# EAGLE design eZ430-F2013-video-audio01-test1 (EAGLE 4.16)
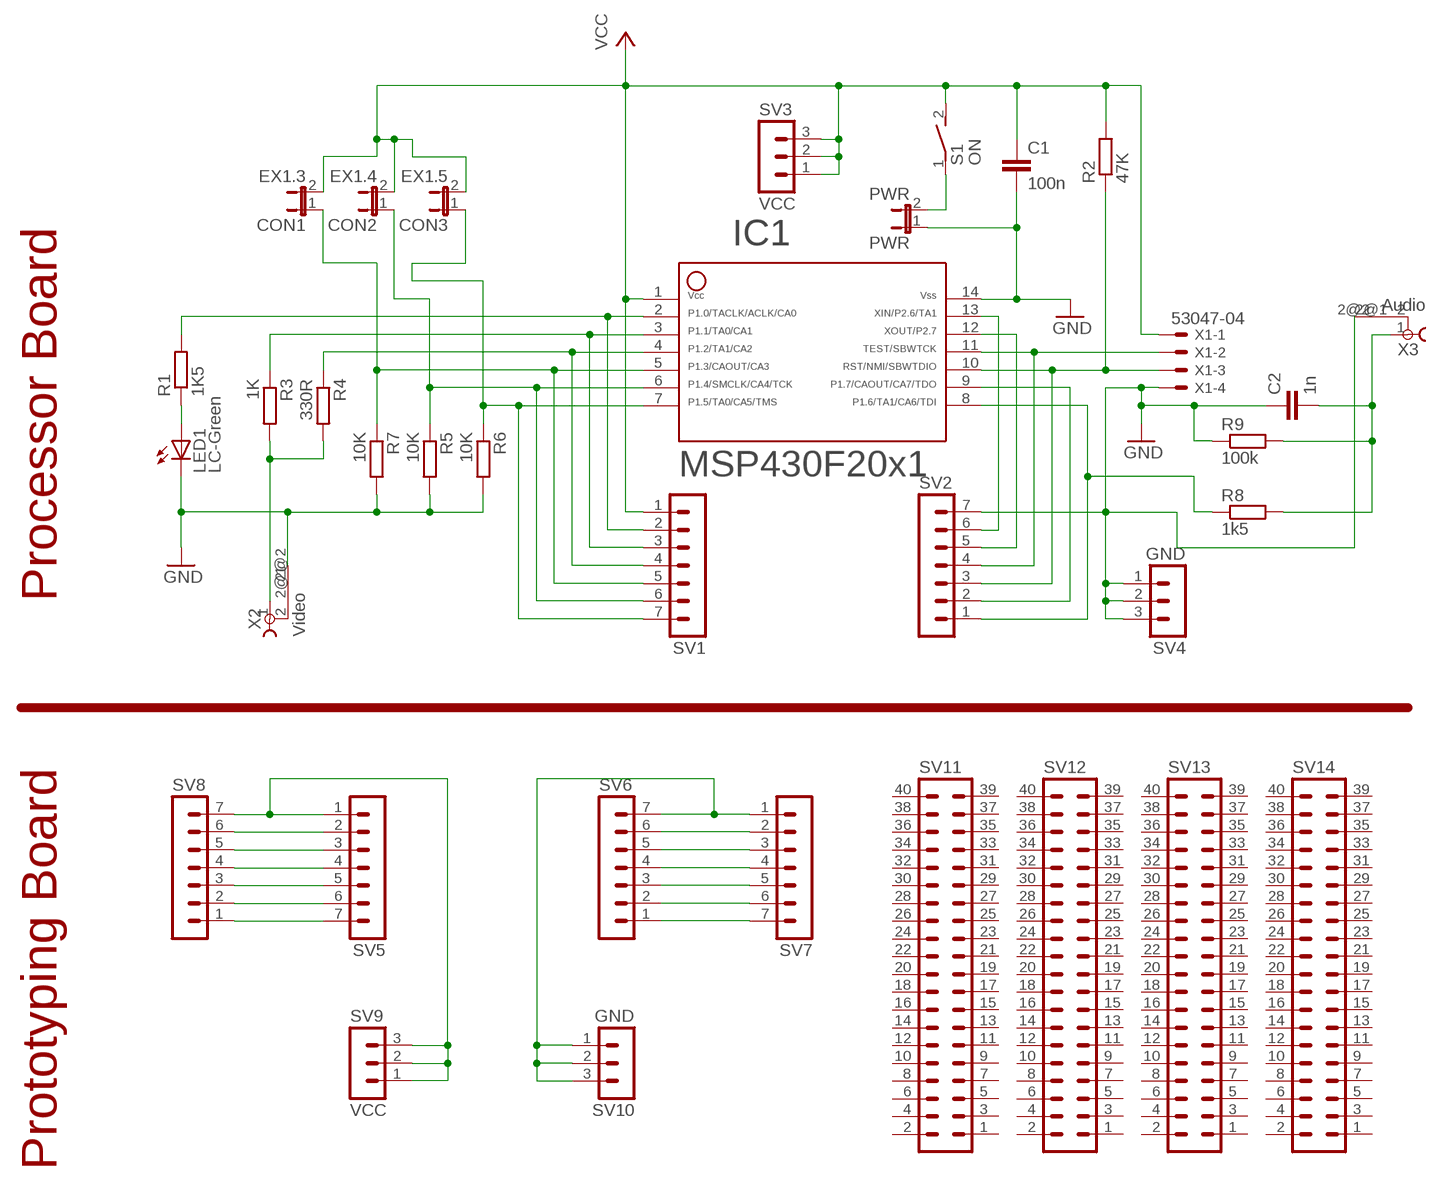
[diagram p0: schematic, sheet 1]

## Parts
C1  100n  C-EU050-030X075  [C050-030X075]
C2  1n  C-EU050-030X075  [C050-030X075]
CON1  EX1.3  JP1E  [JP1]
CON2  EX1.4  JP1E  [JP1]
CON3  EX1.5  JP1E  [JP1]
IC1  F20X1---N14  [N14]
LED1  LC-Green  LED5MM  [LED5MM]
PWR  PWR  JP1E  [JP1]
R1  1K5  R-EU_0204/7  [0204/7]
R2  47K  R-EU_0204/7  [0204/7]
R3  1K  R-EU_0204/7  [0204/7]
R4  330R  R-EU_0204/7  [0204/7]
R5  10K  R-EU_0204/7  [0204/7]
R6  10K  R-EU_0204/7  [0204/7]
R7  10K  R-EU_0204/7  [0204/7]
R8  1k5  R-EU_0204/7  [0204/7]
R9  100k  R-EU_0204/7  [0204/7]
S1  ON  DS01E  [DS-01]
SV1  MA07-1  [MA07-1]
SV2  MA07-1  [MA07-1]
SV3  VCC  MA03-1  [MA03-1]
SV4  GND  MA03-1  [MA03-1]
SV5  MA07-1  [MA07-1]
SV6  MA07-1  [MA07-1]
SV7  MA07-1  [MA07-1]
SV8  MA07-1  [MA07-1]
SV9  VCC  MA03-1  [MA03-1]
SV10  GND  MA03-1  [MA03-1]
SV11  MA20-2  [MA20-2]
SV12  MA20-2  [MA20-2]
SV13  MA20-2  [MA20-2]
SV14  MA20-2  [MA20-2]
X1  53047-04  [53047-04]
X2  Video  TOBU3  [TOBU3]
X3  Audio  TOBU3  [TOBU3]

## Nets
3V_IN: PWR.2 S1.1
AUDIO: C2.2 R8.2 R9.2 X3.1
GND: C1.2 C2.1 IC1.14 LED1.K(C) PWR.1 R5.2 R6.2 R7.2 R9.1 SV2.7 SV4.1 SV4.2 SV4.3 X1.4 X2.2@2 X3.2@2
GND_EX: SV6.7 SV7.1 SV10.1 SV10.2 SV10.3
LED-IN: LED1.A R1.1
N$2: SV6.6 SV7.2
N$3: SV6.5 SV7.3
N$4: SV6.4 SV7.4
N$5: SV6.3 SV7.5
N$6: SV6.2 SV7.6
N$7: SV6.1 SV7.7
N$8: SV5.7 SV8.1
N$9: SV5.6 SV8.2
N$10: SV5.5 SV8.3
N$11: SV5.4 SV8.4
N$12: SV5.3 SV8.5
N$13: SV5.2 SV8.6
P1.0: IC1.2 R1.2 SV1.2
P1.1: IC1.3 R3.1 SV1.3
P1.2: IC1.4 R4.1 SV1.4
P1.3: CON1.1 IC1.5 R7.1 SV1.5
P1.4: CON2.1 IC1.6 R5.1 SV1.6
P1.5: CON3.1 IC1.7 R6.1 SV1.7
P1.6: IC1.8 R8.1 SV2.1
P1.7: IC1.9 SV2.2
SBWTCK: IC1.11 SV2.4 X1.2
SBWTDIO: IC1.10 R2.1 SV2.3 X1.3
VCC: C1.1 CON1.2 CON2.2 CON3.2 IC1.1 R2.2 S1.2 SV1.1 SV3.1 SV3.2 SV3.3 X1.1
VCC-EX: SV5.1 SV8.7 SV9.1 SV9.2 SV9.3
VIDEOOUT: R3.2 R4.2 X2.1
XIN: IC1.13 SV2.6
XOUT: IC1.12 SV2.5
Unconnected: SV11.1 SV11.2 SV11.3 SV11.4 SV11.5 SV11.6 SV11.7 SV11.8 SV11.9 SV11.10 SV11.11 SV11.12 SV11.13 SV11.14 SV11.15 SV11.16 SV11.17 SV11.18 SV11.19 SV11.20 SV11.21 SV11.22 SV11.23 SV11.24 SV11.25 SV11.26 SV11.27 SV11.28 SV11.29 SV11.30 SV11.31 SV11.32 SV11.33 SV11.34 SV11.35 SV11.36 SV11.37 SV11.38 SV11.39 SV11.40 SV12.1 SV12.2 SV12.3 SV12.4 SV12.5 SV12.6 SV12.7 SV12.8 SV12.9 SV12.10 SV12.11 SV12.12 SV12.13 SV12.14 SV12.15 SV12.16 SV12.17 SV12.18 SV12.19 SV12.20 SV12.21 SV12.22 SV12.23 SV12.24 SV12.25 SV12.26 SV12.27 SV12.28 SV12.29 SV12.30 SV12.31 SV12.32 SV12.33 SV12.34 SV12.35 SV12.36 SV12.37 SV12.38 SV12.39 SV12.40 SV13.1 SV13.2 SV13.3 SV13.4 SV13.5 SV13.6 SV13.7 SV13.8 SV13.9 SV13.10 SV13.11 SV13.12 SV13.13 SV13.14 SV13.15 SV13.16 SV13.17 SV13.18 SV13.19 SV13.20 SV13.21 SV13.22 SV13.23 SV13.24 SV13.25 SV13.26 SV13.27 SV13.28 SV13.29 SV13.30 SV13.31 SV13.32 SV13.33 SV13.34 SV13.35 SV13.36 SV13.37 SV13.38 SV13.39 SV13.40 SV14.1 SV14.2 SV14.3 SV14.4 SV14.5 SV14.6 SV14.7 SV14.8 SV14.9 SV14.10 SV14.11 SV14.12 SV14.13 SV14.14 SV14.15 SV14.16 SV14.17 SV14.18 SV14.19 SV14.20 SV14.21 SV14.22 SV14.23 SV14.24 SV14.25 SV14.26 SV14.27 SV14.28 SV14.29 SV14.30 SV14.31 SV14.32 SV14.33 SV14.34 SV14.35 SV14.36 SV14.37 SV14.38 SV14.39 SV14.40 X2.2 X2.2@1 X3.2 X3.2@1

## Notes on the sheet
- Processor Board
- Prototyping Board

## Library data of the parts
C1 C2 = rcl:C-EU: CAPACITOR, European symbol
CON1-CON3 PWR = jumper:JP1E: JUMPER
IC1 = TI_MSP430_v122:F20X1---N14: ***MSP430F20x1***N14
LED1 = led:LED: LED
R1-R9 = rcl:R-EU_: RESISTOR, European symbol
S1 = switch-dil:DS01E: DIL/CODE SWITCH
SV1 SV2 SV5-SV8 = con-lstb:MA07-1: PIN HEADER
SV3 SV4 SV9 SV10 = con-lstb:MA03-1: PIN HEADER
SV11-SV14 = con-lstb:MA20-2: PIN HEADER
X1 = con-molex:53?-04: CONNECTOR wire to board 1.25 mm (.049 inch) pitch header
X2 X3 = con-hirschmann:TOBU3: Female Cinch CONNECTOR

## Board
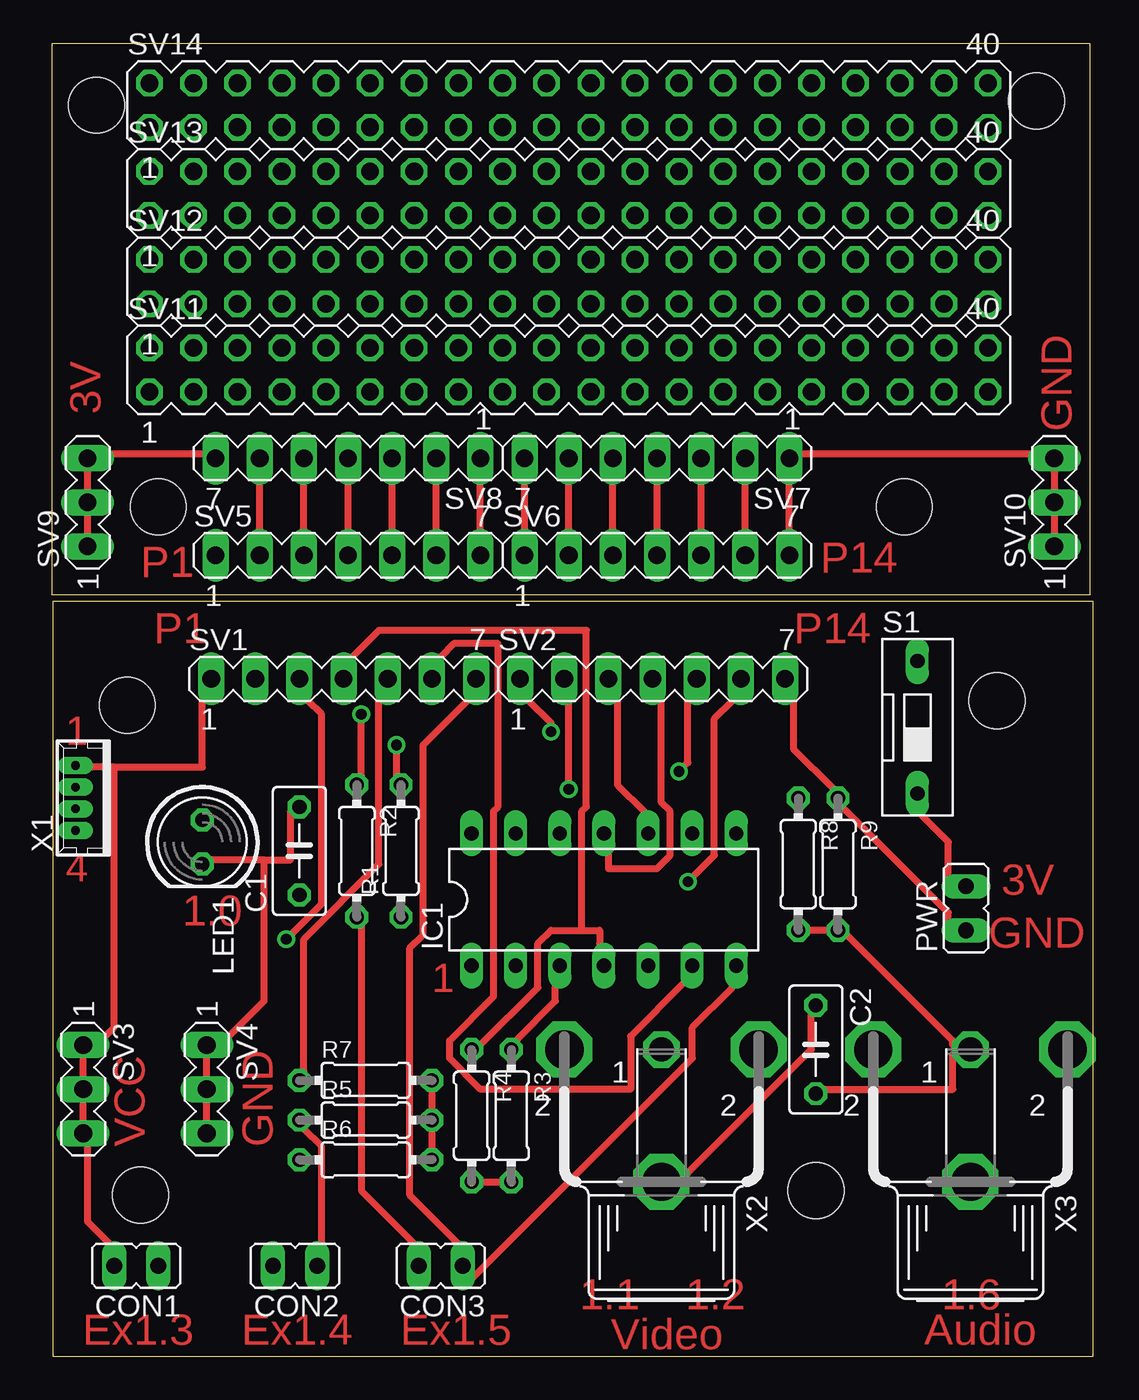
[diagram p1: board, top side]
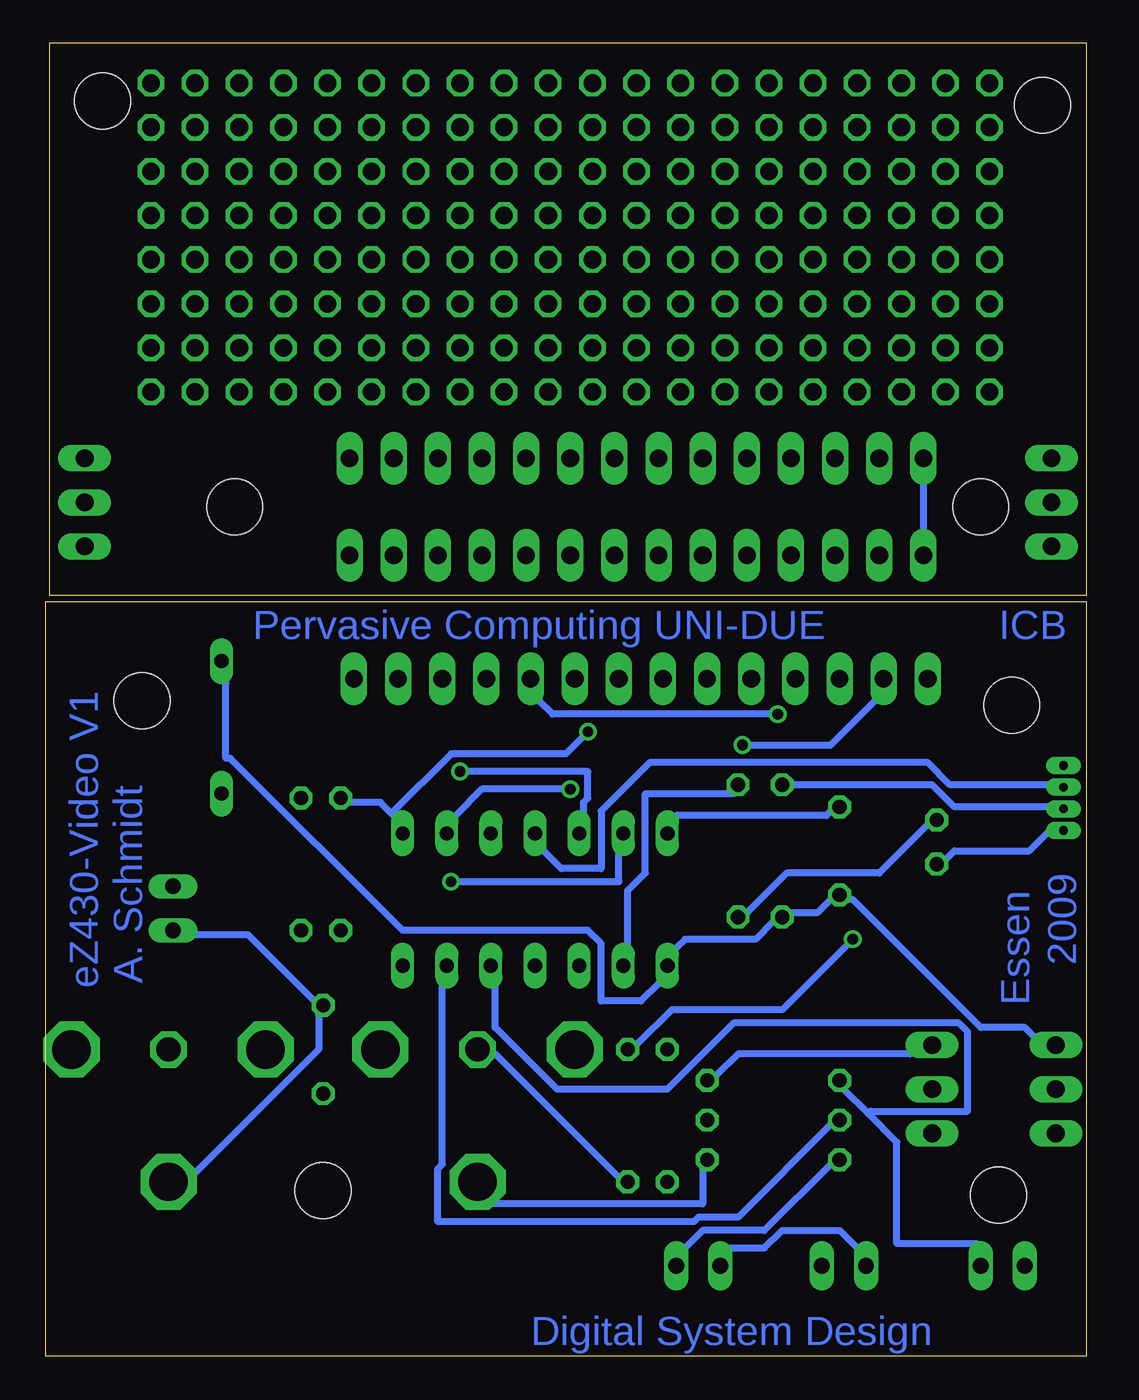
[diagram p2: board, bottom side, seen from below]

Size 59.91 x 75.56 mm. Coordinates in mm from the lower left corner, seen from the top.
Outline: 0.04,0 59.91,0 59.91,43.42 0.04,43.42 0.04,0
Outline: 0,75.56 59.69,75.56 59.69,43.81 0,43.81 0,75.56
Copper layers (1*16): Top 0.035mm / dielectric 1.5mm / Bottom 0.035mm
Design rules "default": minimum track width 16mil, minimum drill 24mil, track to track 12mil, track to pad 12mil, pad to pad 8mil, via to via 8mil, smd to smd 8mil, copper to edge 40mil, drill to drill 8mil, minimum pad ring 10mil, minimum via ring 8mil, stop-mask expansion 4mil, vias tented up to drill 0mil, thermal gap 10mil
Holes 3.2 mm at 4.32,37.46 5.08,9.27 43.94,9.52 54.36,37.71 2.54,72 6.1,48.89 49.02,48.89 56.64,72.26

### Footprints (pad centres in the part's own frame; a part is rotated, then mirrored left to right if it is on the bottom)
C050-030X075 = drill 0.813 octagon: 1 -2.54,0; 2 2.54,0
JP1 = drill 0.914 long: 1 0,-1.27; 2 0,1.27
N14 = drill 0.813 long: 1 -7.625,-3.81; 2 -5.085,-3.81; 3 -2.545,-3.81; 4 -0.005,-3.81; 5 2.535,-3.81; 6 5.075,-3.81; 7 7.615,-3.81; 8 7.615,3.81; 9 5.075,3.81; 10 2.535,3.81; 11 -0.005,3.81; 12 -2.545,3.81; 13 -5.085,3.81; 14 -7.625,3.81
LED5MM = drill 0.813 octagon: A -1.27,0; K 1.27,0
0204/7 = drill 0.813 octagon: 1 -3.81,0; 2 3.81,0
DS-01 = drill 0.813 long: 1 0,-3.81; 2 0,3.81
MA07-1 = drill 1.016 long: 1 -7.62,0; 2 -5.08,0; 3 -2.54,0; 4 0,0; 5 2.54,0; 6 5.08,0; 7 7.62,0
MA03-1 = drill 1.016 long: 1 -2.54,0; 2 0,0; 3 2.54,0
MA20-2 = drill 1.016 octagon: 1 -24.13,-1.27; 2 -24.13,1.27; 3 -21.59,-1.27; 4 -21.59,1.27; 5 -19.05,-1.27; 6 -19.05,1.27; 7 -16.51,-1.27; 8 -16.51,1.27; 9 -13.97,-1.27; 10 -13.97,1.27; 11 -11.43,-1.27; 12 -11.43,1.27; 13 -8.89,-1.27; 14 -8.89,1.27; 15 -6.35,-1.27; 16 -6.35,1.27; 17 -3.81,-1.27; 18 -3.81,1.27; 19 -1.27,-1.27; 20 -1.27,1.27; 21 1.27,-1.27; 22 1.27,1.27; 23 3.81,-1.27; 24 3.81,1.27; 25 6.35,-1.27; 26 6.35,1.27; 27 8.89,-1.27; 28 8.89,1.27; 29 11.43,-1.27; 30 11.43,1.27; 31 13.97,-1.27; 32 13.97,1.27; 33 16.51,-1.27; 34 16.51,1.27; 35 19.05,-1.27; 36 19.05,1.27; 37 21.59,-1.27; 38 21.59,1.27; 39 24.13,-1.27; 40 24.13,1.27
53047-04 = drill 0.5 pad 0.698 long: 1 1.875,0.45; 2 0.625,0.45; 3 -0.625,0.45; 4 -1.875,0.45
TOBU3 = drill 1.397 octagon: 1 0,-2.54 | drill 2.21 octagon: 2 5.588,-2.54; 2@1 -5.588,-2.54; 2@2 0,5.08

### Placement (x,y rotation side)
C1  14.22,29.08 90 top
C2  43.94,17.65 270 top
CON1  4.83,5.2 90 top
CON2  13.97,5.2 90 top
CON3  22.35,5.2 90 top
IC1  31.75,26.28 0 top
LED1  8.64,29.59 270 top
PWR  52.58,25.78 0 top
R1  20.07,29.08 90 top
R2  17.53,29.08 270 top
R3  26.42,13.84 270 top
R4  24.13,13.84 270 top
R5  18.03,13.58 0 top
R6  18.03,11.3 0 top
R7  18.03,15.87 0 top
R8  42.93,28.32 270 top
R9  45.21,28.32 270 top
S1  49.78,36.19 0 top
SV1  16.76,38.98 0 top
SV2  34.54,38.98 0 top
SV3  1.78,15.36 270 top
SV4  8.89,15.36 270 top
SV5  17.02,46.1 0 top
SV6  34.8,46.1 0 top
SV7  34.8,51.68 180 top
SV8  17.02,51.68 180 top
SV9  2.03,49.14 90 top
SV10  57.66,49.14 90 top
SV11  29.72,56.76 0 top
SV12  29.72,61.84 0 top
SV13  29.72,66.92 0 top
SV14  29.72,72 0 top
X1  1.78,32.13 90 top
X2  35.05,15.11 180 top
X3  52.83,15.11 180 top

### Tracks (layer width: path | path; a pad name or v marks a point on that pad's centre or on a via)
3V_IN
  Top 0.406: S1.1 50.04,31.11 51.56,29.59 51.56,27.55 PWR.2
AUDIO
  Top 0.406: R8.2 R9.2 45.72,24.25 51.82,18.16 51.82,17.9 X3.1 51.82,17.39 51.82,15.36 44.45,15.36 C2.2
GND
  Top 0.406: R6.2 R5.2 R7.2 | SV4.3 SV4.2 SV4.1 10.16,18.41 12.19,20.44 12.19,28.57 | 12.19,28.57 13.72,28.57 13.72,31.36 C1.2 | 12.19,28.57 9.14,28.57 LED1.K | SV2.7 42.67,37.71 42.67,34.92 44.96,32.63 R9.1 45.47,31.62 51.56,25.52 51.56,25.01 PWR.1 | X2.2@2 36.58,10.54 43.69,17.65 43.69,19.68 C2.1
  Bottom 0.406: R7.2 21.34,16.12 20.07,17.39 10.16,17.39 SV4.1 | X1.4 2.29,30.09 3.3,29.08 7.62,29.08 8.13,28.57 LED1.K | C1.2 14.73,31.36 14.99,31.11 23.62,31.11 IC1.14 | PWR.1 51.31,24.25 48.26,24.25 44.45,20.44 C2.1 44.2,19.68 44.2,17.65 51.31,10.54 X3.2@2 | R6.2 22.1,10.79 22.1,8.76 34.29,8.76 X2.2@2
GND_EX
  Top 0.406: SV10.1 SV10.2 SV10.3 56.39,51.94 42.93,51.94 SV7.1 SV6.7
LED-IN
  Bottom 0.406: LED1.A 9.14,30.6 11.94,27.81 17.27,27.81 19.56,25.52 R1.1
N$2
  Top 0.406: SV6.6 SV7.2
N$3
  Top 0.406: SV6.5 SV7.3
N$4
  Top 0.406: SV6.4 SV7.4
N$5
  Top 0.406: SV6.3 SV7.5
N$6
  Top 0.406: SV6.2 SV7.6
N$7
  Top 0.406: SV6.1 SV7.7
N$8
  Top 0.406: SV5.7 SV8.1
N$9
  Top 0.406: SV5.6 SV8.2
N$10
  Top 0.406: SV5.5 SV8.3
N$11
  Top 0.406: SV5.4 SV8.4
N$12
  Top 0.406: SV5.3 SV8.5
N$13
  Top 0.406: SV5.2 SV8.6
P1.0  (via drill 0.61)
  Top 0.406: v19.81,35.17 19.81,33.4 R1.2
  Bottom 0.406: IC1.2 26.42,23.74 26.42,26.79 25.4,27.81 25.4,32.38 20.32,32.38 R1.2 | v19.81,35.17 14.73,35.17 12.19,37.71 SV1.2
P1.1  (via drill 0.61)
  Top 0.406: R3.1 26.67,18.16 28.96,20.44 28.96,21.2 IC1.3 | v13.46,24 15.49,26.03 15.49,36.95 14.73,37.71 SV1.3
  Bottom 0.406: v13.46,24 17.53,19.93 23.88,19.93 25.91,17.9 R3.1
P1.2
  Top 0.406: 30.48,24.51 31.5,24.51 31.5,23.74 IC1.4 | 30.48,24.51 28.7,24.51 27.94,23.74 27.94,21.2 24.64,17.9 R4.1 | 30.48,24.51 30.48,31.36 30.73,31.62 30.73,41.78 18.8,41.78 17.27,40.25 SV1.4
P1.3
  Top 0.406: SV1.5 18.8,37.71 18.8,28.32 14.48,24 14.48,16.38 R7.1
  Bottom 0.406: 12.57,13.96 10.92,12.31 10.92,6.47 6.35,6.47 CON1.1 | 12.57,13.96 13.97,15.36 R7.1 | IC1.5 34.04,21.2 34.04,18.92 30.48,15.36 24.13,15.36 20.32,19.17 7.37,19.17 6.86,18.66 6.86,14.09 12.45,14.09 12.57,13.96
P1.4
  Top 0.406: R5.1 14.48,13.08 15.49,12.06 15.49,6.47 CON2.1 | SV1.6 22.35,40.25 23.11,41.02 25.65,41.02 25.65,31.62 25.4,31.36 25.4,20.7 22.86,18.16 22.86,17.14 24.64,15.36 33.27,15.36 33.27,18.41 36.32,21.46 IC1.6
  Bottom 0.406: IC1.6 37.08,21.2 37.08,11.04 37.34,10.79 37.34,7.74 22.61,7.74 22.35,8 20.07,8 14.73,13.33 R5.1
P1.5
  Top 0.406: IC1.7 39.12,21.2 36.83,18.92 36.83,17.14 24.13,4.44 CON3.1 23.37,6.47 20.57,9.27 20.57,23.49 21.34,24.25 21.34,35.17 23.88,37.71 SV1.7
  Bottom 0.406: R6.1 14.73,11.04 18.54,7.23 22.1,7.23 23.11,6.22 CON3.1
P1.6  (via drill 0.61)
  Top 0.406: v28.7,35.94 28.7,36.44 27.43,37.71 SV2.1
  Bottom 0.406: 40.01,31.24 40.64,31.87 42.42,31.87 R8.1 | 40.01,31.24 39.88,31.11 IC1.8 | v28.7,35.94 29.97,34.67 36.58,34.67 40.01,31.24
P1.7  (via drill 0.61)
  Top 0.406: v29.72,32.63 29.72,37.71 SV2.2
  Bottom 0.406: v29.72,32.63 34.8,32.63 36.32,31.11 IC1.9
SBWTCK
  Top 0.406: SV2.4 35.05,37.71 35.05,31.87 35.56,31.36 35.56,28.82 34.8,28.06 32,28.06 32,28.82 IC1.11
  Bottom 0.406: X1.2 2.29,32.89 7.87,32.89 9.14,34.16 25.15,34.16 27.94,31.36 27.94,28.06 30.23,28.06 31.24,29.08 IC1.11
SBWTDIO  (via drill 0.61)
  Top 0.406: IC1.10 34.04,31.36 32.51,32.89 32.51,37.71 SV2.3 | v17.78,36.95 17.78,33.4 R2.1
  Bottom 0.406: X1.3 2.29,31.62 7.62,31.62 8.89,32.89 R2.1 | v17.78,36.95 30.73,36.95 31.5,37.71 SV2.3
VCC
  Top 0.406: 3.56,33.9 8.64,33.9 8.64,37.71 SV1.1 | 3.56,33.9 2.29,33.9 X1.1 | CON1.2 3.3,6.47 2.03,7.74 2.03,12.31 SV3.3 SV3.2 SV3.1 3.05,18.41 3.56,18.92 3.56,33.9 | CON3.2 20.83,6.47 17.78,9.52 17.78,24.76 R2.2
  Bottom 0.406: CON2.2 13.21,6.22 14.22,7.23 17.53,7.23 18.54,6.22 20.57,6.22 CON3.2 | S1.2 49.53,38.73 49.53,34.41 49.28,34.41 39.37,24.51 28.7,24.51 27.94,23.74 27.94,20.44 25.65,20.44 24.64,21.46 IC1.1 23.62,23.49 23.11,24 19.05,24 18.03,25.01 R2.2 17.02,25.52 15.49,25.52 14.73,26.28 C1.1 13.72,26.28 13.46,26.28 6.1,18.92 3.56,18.92 3.05,18.41 SV3.1
VCC-EX
  Top 0.406: SV9.1 SV9.2 SV9.3 3.3,51.94 8.89,51.94 SV8.7
  Bottom 0.406: SV8.7 SV5.1
VIDEOOUT
  Top 0.406: R4.2 R3.2
  Bottom 0.406: R3.2 26.92,10.28 34.04,17.39 X2.1
XIN  (via drill 0.61)
  Top 0.406: v36.58,27.3 38.1,28.82 38.1,36.7 39.12,37.71 SV2.6
  Bottom 0.406: v36.58,27.3 26.92,27.3 26.92,28.82 IC1.13
XOUT  (via drill 0.61)
  Top 0.406: v36.07,33.65 36.58,34.16 36.58,37.71 SV2.5
  Bottom 0.406: v36.07,33.65 28.7,33.65 28.7,32.13 28.96,31.87 28.96,31.36 IC1.12

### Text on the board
Top: GND | 3V | P1 | P14 | P1 | P14 | 1 | 3V | 4 | 1.0 | GND | 1 | VCC | GND | 1.1 | 1.2 | 1.6 | Ex1.3 | Ex1.4 | Ex1.5 | Video | Audio
Bottom: ICB | Pervasive Computing UNI-DUE | 2009 | A. Schmidt | eZ430-Video V1 | Essen | Digital System Design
